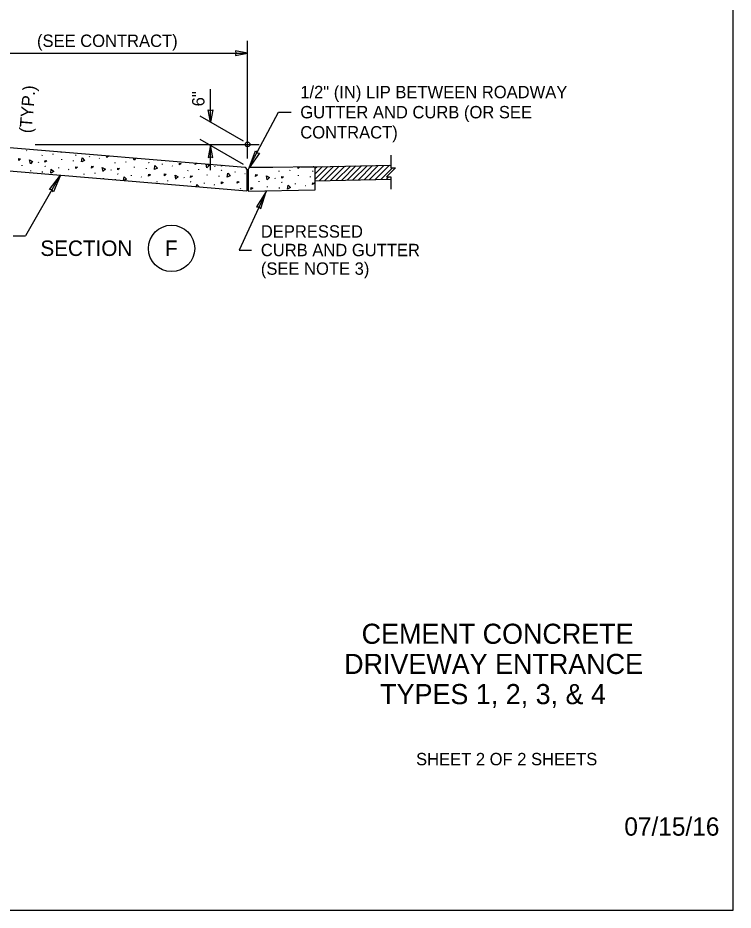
# Model space of a CAD drawing. Extents: x 99862 to 103151, y 100000 to 105076.
# Drawn here: x 102226 to 103151, y 103000 to 104153 of the extents above; entities that cross this region are included whole.
import ezdxf

# ---------------------------------------------------------------- set-up
doc = ezdxf.new("R2010")
doc.units = 0
for name, color, linetype in [('Level 1', 7, 'Continuous'), ('Level 13', 7, 'Continuous'), ('Level 15', 7, 'Continuous'), ('Level 20', 7, 'Continuous'), ('Level 48', 7, 'Continuous'), ('Level 62', 7, 'Continuous'), ('Level 9', 7, 'Continuous')]:
    doc.layers.add(name, color=color, linetype=linetype)

msp = doc.modelspace()

# ---------------------------------------------------------------- linework, layer by layer
at = {"layer": 'Level 1'}
msp.add_lwpolyline([(99862, 102999.5), (103151, 102999.5), (103151, 105075.5), (99862, 105075.5)], close=True, dxfattribs=at)
at = {"layer": 'Level 13'}
for p, q in [((102237.4, 103981.6), (102237.9, 103981.2)), ((102237.4, 103981.6), (102237.9, 103981.2)), ((102257.9, 103975), (102258, 103975.9)), ((102257.9, 103975), (102258, 103975.9)), ((102271.9, 103976.2), (102271.9, 103977.1)), ((102271.9, 103976.2), (102271.9, 103977.1)), ((102283, 103969.3), (102283, 103970.2)), ((102283, 103969.3), (102283, 103970.2)), ((102298.3, 103967.8), (102298.3, 103968.7)), ((102298.3, 103967.8), (102298.3, 103968.7)), ((102300.9, 103975.8), (102301.4, 103975.4)), ((102300.9, 103975.8), (102301.4, 103975.4)), ((102301.3, 103975.7), (102301.8, 103975.4)), ((102301.3, 103975.7), (102301.8, 103975.4)), ((102319.1, 103973.3), (102319.2, 103974.1)), ((102319.1, 103973.3), (102319.2, 103974.1)), ((102331.5, 103971.7), (102332, 103971.3)), ((102331.5, 103971.7), (102332, 103971.3)), ((102386.9, 103970.8), (102387, 103970.7)), ((102386.9, 103970.8), (102387, 103970.7)), ((102231.9, 103961.6), (102232, 103962.5)), ((102231.9, 103961.6), (102232, 103962.5)), ((102252.5, 103966.8), (102252.9, 103966.1)), ((102252.5, 103966.8), (102252.9, 103966.1)), ((102261, 103961.3), (102261.5, 103960.9)), ((102261, 103961.3), (102261.5, 103960.9)), ((102261.4, 103961.2), (102261.9, 103960.8)), ((102261.4, 103961.2), (102261.9, 103960.8)), ((102279.2, 103958.7), (102279.2, 103959.6)), ((102279.2, 103958.7), (102279.2, 103959.6)), ((102291.5, 103957.2), (102292.1, 103956.8)), ((102291.5, 103957.2), (102292.1, 103956.8)), ((102346.6, 103956.9), (102347, 103956.2)), ((102346.6, 103956.9), (102347, 103956.2)), ((102352.1, 103965.1), (102352.1, 103966)), ((102352.1, 103965.1), (102352.1, 103966)), ((102366, 103966.3), (102366.1, 103967.2)), ((102366, 103966.3), (102366.1, 103967.2)), ((102377.1, 103959.4), (102377.2, 103960.3)), ((102377.1, 103959.4), (102377.2, 103960.3)), ((102392.4, 103957.9), (102392.4, 103958.8)), ((102392.4, 103957.9), (102392.4, 103958.8)), ((102395.1, 103965.9), (102395.6, 103965.5)), ((102395.1, 103965.9), (102395.6, 103965.5)), ((102395.5, 103965.9), (102396, 103965.5)), ((102395.5, 103965.9), (102396, 103965.5)), ((102413.3, 103963.4), (102413.3, 103964.3)), ((102413.3, 103963.4), (102413.3, 103964.3)), ((102425.7, 103961.8), (102426.2, 103961.5)), ((102425.7, 103961.8), (102426.2, 103961.5)), ((102460.1, 103956.4), (102460.2, 103957.3)), ((102460.1, 103956.4), (102460.2, 103957.3)), ((102480.7, 103961.6), (102481.1, 103960.8)), ((102480.7, 103961.6), (102481.1, 103960.8)), ((102578, 103955.5), (102578.1, 103956.4)), ((102578, 103955.5), (102578.1, 103956.4)), ((102598.8, 103960.3), (102599, 103959.9)), ((102598.8, 103960.3), (102599, 103959.9)), ((102243, 103954.7), (102243.1, 103955.6)), ((102243, 103954.7), (102243.1, 103955.6)), ((102258.3, 103953.3), (102258.3, 103954.2)), ((102258.3, 103953.3), (102258.3, 103954.2)), ((102312.1, 103950.6), (102312.2, 103951.4)), ((102312.1, 103950.6), (102312.2, 103951.4)), ((102326, 103951.8), (102326.1, 103952.6)), ((102326, 103951.8), (102326.1, 103952.6)), ((102337.1, 103944.9), (102337.2, 103945.7)), ((102337.1, 103944.9), (102337.2, 103945.7)), ((102355.1, 103951.4), (102355.6, 103951)), ((102355.1, 103951.4), (102355.6, 103951)), ((102355.5, 103951.3), (102356, 103950.9)), ((102355.5, 103951.3), (102356, 103950.9)), ((102373.3, 103948.8), (102373.4, 103949.7)), ((102373.3, 103948.8), (102373.4, 103949.7)), ((102385.7, 103947.3), (102386.2, 103946.9)), ((102385.7, 103947.3), (102386.2, 103946.9)), ((102440.8, 103947), (102441.1, 103946.3)), ((102440.8, 103947), (102441.1, 103946.3)), ((102446.2, 103955.2), (102446.3, 103956.1)), ((102446.2, 103955.2), (102446.3, 103956.1)), ((102471.2, 103949.5), (102471.3, 103950.4)), ((102471.2, 103949.5), (102471.3, 103950.4)), ((102486.5, 103948.1), (102486.6, 103948.9)), ((102486.5, 103948.1), (102486.6, 103948.9)), ((102489.2, 103956), (102489.7, 103955.7)), ((102489.2, 103956), (102489.7, 103955.7)), ((102489.6, 103956), (102490.1, 103955.6)), ((102489.6, 103956), (102490.1, 103955.6)), ((102507.4, 103953.5), (102507.5, 103954.4)), ((102507.4, 103953.5), (102507.5, 103954.4)), ((102519.8, 103952), (102520.3, 103951.6)), ((102519.8, 103952), (102520.3, 103951.6)), ((102558.7, 103946.1), (102559, 103945.4)), ((102558.7, 103946.1), (102559, 103945.4)), ((102564.1, 103954.3), (102564.2, 103955.2)), ((102564.1, 103954.3), (102564.2, 103955.2)), ((102589.1, 103948.6), (102589.2, 103949.5)), ((102589.1, 103948.6), (102589.2, 103949.5)), ((102604.4, 103947.1), (102604.5, 103948)), ((102604.4, 103947.1), (102604.5, 103948)), ((102607.1, 103955.1), (102607.6, 103954.7)), ((102607.1, 103955.1), (102607.6, 103954.7)), ((102607.5, 103955), (102608, 103954.7)), ((102607.5, 103955), (102608, 103954.7)), ((102352.4, 103943.7), (102352.5, 103944.3)), ((102352.4, 103943.7), (102352.5, 103944.3)), ((102406.2, 103940.7), (102406.3, 103941.6)), ((102406.2, 103940.7), (102406.3, 103941.6)), ((102420.2, 103941.9), (102420.2, 103942.8)), ((102420.2, 103941.9), (102420.2, 103942.8)), ((102449.2, 103941.5), (102449.7, 103941.1)), ((102449.2, 103941.5), (102449.7, 103941.1)), ((102449.6, 103941.4), (102450.1, 103941)), ((102449.6, 103941.4), (102450.1, 103941)), ((102467.4, 103938.9), (102467.5, 103939.8)), ((102467.4, 103938.9), (102467.5, 103939.8)), ((102479.8, 103937.4), (102480.3, 103937)), ((102479.8, 103937.4), (102480.3, 103937)), ((102524.2, 103940.5), (102524.2, 103940.6)), ((102524.2, 103940.5), (102524.2, 103940.6)), ((102538.1, 103941), (102538.1, 103941.8)), ((102538.1, 103941), (102538.1, 103941.8)), ((102549.2, 103934), (102549.2, 103934.9)), ((102549.2, 103934), (102549.2, 103934.9)), ((102564.4, 103932.6), (102564.5, 103933.5)), ((102564.4, 103932.6), (102564.5, 103933.5)), ((102567.1, 103940.6), (102567.6, 103940.2)), ((102567.1, 103940.6), (102567.6, 103940.2)), ((102567.5, 103940.5), (102568, 103940.1)), ((102567.5, 103940.5), (102568, 103940.1)), ((102585.3, 103938), (102585.4, 103938.9)), ((102585.3, 103938), (102585.4, 103938.9)), ((102597.7, 103936.5), (102598.2, 103936.1)), ((102597.7, 103936.5), (102598.2, 103936.1)), ((102500.4, 103931.3), (102500.4, 103931.7)), ((102500.4, 103931.3), (102500.4, 103931.7)), ((102514.3, 103932), (102514.4, 103932.9)), ((102514.3, 103932), (102514.4, 103932.9))]:
    msp.add_line(p, q, dxfattribs=at)
for points in [[(102282.3, 103979), (102282.2, 103979.5)], [(102282.3, 103979), (102282.2, 103979.5)], [(102282.8, 103979.5), (102282.4, 103979.1)], [(102282.8, 103979.5), (102282.4, 103979.1)], [(102227.4, 103968.8), (102227.7, 103971.2), (102229.8, 103970.6), (102227.4, 103968.8)], [(102227.4, 103968.8), (102227.7, 103971.2), (102229.8, 103970.6), (102227.4, 103968.8)], [(102242.4, 103964.5), (102241.3, 103969.5), (102245.4, 103967.5), (102242.4, 103964.5)], [(102242.4, 103964.5), (102241.3, 103969.5), (102245.4, 103967.5), (102242.4, 103964.5)], [(102261.3, 103966.3), (102261.5, 103968.7), (102263.7, 103968.1), (102261.3, 103966.3)], [(102261.3, 103966.3), (102261.5, 103968.7), (102263.7, 103968.1), (102261.3, 103966.3)], [(102308.7, 103966.9), (102309.4, 103972), (102312.6, 103968.7), (102308.8, 103966.9)], [(102308.7, 103966.9), (102309.4, 103972), (102312.6, 103968.7), (102308.8, 103966.9)], [(102341.1, 103972.7), (102341.3, 103974.6)], [(102341.1, 103972.7), (102341.3, 103974.6)], [(102343.3, 103974.4), (102341.1, 103972.7)], [(102343.3, 103974.4), (102341.1, 103972.7)], [(102376.5, 103969.1), (102375.9, 103971.7)], [(102376.5, 103969.1), (102375.9, 103971.7)], [(102378.8, 103971.5), (102376.5, 103969.2)], [(102378.8, 103971.5), (102376.5, 103969.2)], [(102268.7, 103952.4), (102269.4, 103957.4), (102272.6, 103954.2), (102268.8, 103952.4)], [(102268.7, 103952.4), (102269.4, 103957.4), (102272.6, 103954.2), (102268.8, 103952.4)], [(102301.1, 103958.2), (102301.3, 103960.6), (102303.5, 103960), (102301.1, 103958.2)], [(102301.1, 103958.2), (102301.3, 103960.6), (102303.5, 103960), (102301.1, 103958.2)], [(102321.6, 103958.9), (102321.8, 103961.3), (102323.9, 103960.7), (102321.6, 103958.9)], [(102321.6, 103958.9), (102321.8, 103961.3), (102323.9, 103960.7), (102321.6, 103958.9)], [(102336.5, 103954.6), (102335.4, 103959.6), (102339.5, 103957.6), (102336.6, 103954.7)], [(102336.5, 103954.6), (102335.4, 103959.6), (102339.5, 103957.6), (102336.6, 103954.7)], [(102355.4, 103956.4), (102355.7, 103958.9), (102357.8, 103958.2), (102355.4, 103956.4)], [(102355.4, 103956.4), (102355.7, 103958.9), (102357.8, 103958.2), (102355.4, 103956.4)], [(102402.8, 103957), (102403.5, 103962.1), (102406.7, 103958.8), (102402.9, 103957.1)], [(102402.8, 103957), (102403.5, 103962.1), (102406.7, 103958.8), (102402.9, 103957.1)], [(102435.2, 103962.9), (102435.4, 103965.3), (102437.6, 103964.7), (102435.2, 103962.9)], [(102435.2, 103962.9), (102435.4, 103965.3), (102437.6, 103964.7), (102435.2, 103962.9)], [(102455.7, 103963.5), (102455.8, 103965)], [(102455.7, 103963.5), (102455.8, 103965)], [(102457.4, 103964.9), (102455.7, 103963.5)], [(102457.4, 103964.9), (102455.7, 103963.5)], [(102470.6, 103959.3), (102469.6, 103963.9)], [(102470.6, 103959.3), (102469.6, 103963.9)], [(102470.5, 103963.8), (102473.6, 103962.3), (102470.7, 103959.3)], [(102470.5, 103963.8), (102473.6, 103962.3), (102470.7, 103959.3)], [(102489.5, 103961.1), (102489.6, 103962.2)], [(102489.5, 103961.1), (102489.6, 103962.2)], [(102490.9, 103962.1), (102489.5, 103961.1)], [(102490.9, 103962.1), (102489.5, 103961.1)], [(102524.5, 103958), (102524.6, 103957.9), (102524.4, 103957.8)], [(102524.5, 103958), (102524.6, 103957.9), (102524.4, 103957.8)], [(102588.5, 103958.3), (102588.1, 103960.1)], [(102588.5, 103958.3), (102588.1, 103960.1)], [(102590.3, 103960.1), (102588.6, 103958.4)], [(102590.3, 103960.1), (102588.6, 103958.4)], [(102607.4, 103960.2), (102607.5, 103960.5)], [(102607.8, 103960.5), (102607.4, 103960.2)], [(102607.4, 103960.2), (102607.5, 103960.5)], [(102607.8, 103960.5), (102607.4, 103960.2)], [(102362.9, 103942.8), (102363.6, 103947.6), (102366.7, 103944.3), (102363.4, 103942.7)], [(102395.2, 103948.3), (102395.5, 103950.8), (102397.6, 103950.1), (102395.2, 103948.3)], [(102395.2, 103948.3), (102395.5, 103950.8), (102397.6, 103950.1), (102395.2, 103948.3)], [(102415.7, 103949), (102415.9, 103951.5), (102418.1, 103950.8), (102415.7, 103949)], [(102415.7, 103949), (102415.9, 103951.5), (102418.1, 103950.8), (102415.7, 103949)], [(102430.6, 103944.7), (102429.5, 103949.7), (102433.7, 103947.7), (102430.7, 103944.8)], [(102430.6, 103944.7), (102429.5, 103949.7), (102433.7, 103947.7), (102430.7, 103944.8)], [(102449.6, 103946.5), (102449.8, 103949), (102451.9, 103948.3), (102449.6, 103946.5)], [(102449.6, 103946.5), (102449.8, 103949), (102451.9, 103948.3), (102449.6, 103946.5)], [(102497, 103947.1), (102497.7, 103952.2), (102500.8, 103948.9), (102497, 103947.2)], [(102497, 103947.1), (102497.7, 103952.2), (102500.8, 103948.9), (102497, 103947.2)], [(102533.6, 103948.1), (102533.8, 103950.5), (102536, 103949.9), (102533.6, 103948.1)], [(102533.6, 103948.1), (102533.8, 103950.5), (102536, 103949.9), (102533.6, 103948.1)], [(102548.5, 103943.8), (102547.5, 103948.8), (102551.6, 103946.8), (102548.6, 103943.8)], [(102548.5, 103943.8), (102547.5, 103948.8), (102551.6, 103946.8), (102548.6, 103943.8)], [(102567.5, 103945.6), (102567.7, 103948.1), (102569.8, 103947.4), (102567.5, 103945.6)], [(102567.5, 103945.6), (102567.7, 103948.1), (102569.8, 103947.4), (102567.5, 103945.6)], [(102457.3, 103934.9), (102457.7, 103937.7), (102460.6, 103934.6)], [(102457.3, 103934.9), (102457.7, 103937.7), (102460.6, 103934.6)], [(102489.4, 103938.4), (102489.6, 103940.9), (102491.7, 103940.2), (102489.4, 103938.4)], [(102489.4, 103938.4), (102489.6, 103940.9), (102491.7, 103940.2), (102489.4, 103938.4)], [(102509.8, 103939.1), (102510.1, 103941.6), (102512.2, 103940.9), (102509.8, 103939.1)], [(102509.8, 103939.1), (102510.1, 103941.6), (102512.2, 103940.9), (102509.8, 103939.1)], [(102527.5, 103931.1), (102527.7, 103933.5), (102529.9, 103932.9), (102527.5, 103931.1)], [(102527.5, 103931.1), (102527.7, 103933.5), (102529.9, 103932.9), (102527.5, 103931.1)], [(102574.9, 103931.7), (102575.6, 103936.7), (102578.8, 103933.5), (102575, 103931.7)], [(102574.9, 103931.7), (102575.6, 103936.7), (102578.8, 103933.5), (102575, 103931.7)], [(102607.3, 103937.5), (102607.5, 103939.9), (102609.6, 103939.3), (102607.3, 103937.5)], [(102607.3, 103937.5), (102607.5, 103939.9), (102609.6, 103939.3), (102607.3, 103937.5)]]:
    msp.add_lwpolyline(points, dxfattribs=at)
at = {"layer": 'Level 15'}
for p, q in [((102523.2, 103971.4), (102523.2, 104123.4)), ((102523.2, 103971.4), (102523.2, 104123.4)), ((102163.2, 104107.4), (102523.2, 104107.4)), ((102475.5, 104018.3), (102475.5, 104060.9)), ((102475.5, 104018.3), (102475.5, 104060.9)), ((102461.6, 104026.3), (102517.7, 103993.9)), ((102525.7, 103960.8), (102563.4, 104031.1)), ((102525.7, 103960.8), (102563.4, 104031.1)), ((102563.4, 104031.1), (102579.4, 104031.1)), ((102563.4, 104031.1), (102579.4, 104031.1)), ((102461.6, 103996.3), (102517.7, 103963.9)), ((102248.5, 103989.4), (102502.9, 103989.4)), ((102475.5, 103956.3), (102475.5, 103988.3)), ((102475.5, 103956.3), (102475.5, 103988.3)), ((102502.9, 103989.4), (102538.2, 103989.4)), ((102511.7, 103989.4), (102538.2, 103989.4)), ((102610.7, 103958.5), (102612.8, 103960.6)), ((102280.7, 103948.6), (102236, 103871.2)), ((102547.1, 103928.4), (102512.4, 103852.9)), ((102547.1, 103928.4), (102512.4, 103852.9)), ((102220, 103871.2), (102236, 103871.2)), ((102512.4, 103852.9), (102528.4, 103852.9)), ((102512.4, 103852.9), (102528.4, 103852.9))]:
    msp.add_line(p, q, dxfattribs=at)
for points in [[(102523.2, 104107.4), (102507.5, 104110.5), (102508.2, 104107.4), (102507.5, 104104.3)], [(102523.2, 104107.4), (102507.5, 104110.5), (102508.2, 104107.4), (102507.5, 104104.3)], [(102475.5, 104018.3), (102472.4, 104034), (102475.5, 104033.3), (102478.5, 104034)], [(102475.5, 104018.3), (102472.4, 104034), (102475.5, 104033.3), (102478.5, 104034)], [(102475.5, 103988.3), (102472.4, 103972.6), (102475.5, 103973.3), (102478.5, 103972.6)], [(102475.5, 103988.3), (102472.4, 103972.6), (102475.5, 103973.3), (102478.5, 103972.6)], [(102525.2, 103959.3), (102533.3, 103980.9), (102535.5, 103978.5), (102538.6, 103978.1)], [(102525.2, 103959.3), (102533.3, 103980.9), (102535.5, 103978.5), (102538.6, 103978.1)], [(102281.3, 103949.6), (102272.4, 103928.3), (102270.4, 103930.7), (102267.3, 103931.3)], [(102547.1, 103928.4), (102534.9, 103908.9), (102538, 103908.6), (102540.3, 103906.4)], [(102547.1, 103928.4), (102534.9, 103908.9), (102538, 103908.6), (102540.3, 103906.4)]]:
    msp.add_lwpolyline(points, close=True, dxfattribs=at)
msp.add_lwpolyline([(102708.6, 103975.3), (102708.6, 103959.3), (102714.4, 103959.3), (102702.8, 103947.7), (102708.6, 103947.7), (102708.6, 103931.7)], dxfattribs=at)
msp.add_lwpolyline([(102708.6, 103975.3), (102708.6, 103959.3), (102714.4, 103959.3), (102702.8, 103947.7), (102708.6, 103947.7), (102708.6, 103931.7)], dxfattribs=at)
msp.add_circle((102523.2, 103989.4), 3.08, dxfattribs=at)
msp.add_circle((102523.2, 103989.4), 3.08, dxfattribs=at)
at = {"layer": 'Level 20'}
for p, q in [((102520, 103959.7), (102166, 103989.2)), ((102163.2, 103959.4), (102522.3, 103929.5)), ((102522.3, 103957.2), (102522.3, 103929.5)), ((102524.2, 103956.9), (102524.2, 103928.8)), ((102555.7, 103959.4), (102526.7, 103959.4)), ((102608.2, 103960.5), (102555.7, 103959.4)), ((102610.7, 103930.5), (102610.7, 103958)), ((102610.7, 103930.5), (102610.7, 103958)), ((102524.2, 103928.8), (102610.7, 103930.5))]:
    msp.add_line(p, q, dxfattribs=at)
for centre, start, end in [((102519.8, 103957.2), 0, 85.2364), ((102519.8, 103957.2), 0, 85.2364), ((102526.7, 103956.9), 90, 180), ((102526.7, 103956.9), 90, 180), ((102608.2, 103958), 0, 91.1458), ((102608.2, 103958), 0, 91.1458)]:
    msp.add_arc(centre, 2.5, start, end, dxfattribs=at)
at = {"layer": 'Level 48'}
for p, q in [((102592, 103960.1), (102708.6, 103962.5)), ((102610.7, 103960.5), (102708.6, 103962.5)), ((102610.7, 103944.4), (102627.2, 103960.8)), ((102610.7, 103951.4), (102620, 103960.7)), ((102616.1, 103942.6), (102634.4, 103961)), ((102623.3, 103942.8), (102641.7, 103961.1)), ((102630.5, 103942.9), (102648.9, 103961.3)), ((102637.7, 103943.1), (102656.1, 103961.4)), ((102644.9, 103943.2), (102663.3, 103961.6)), ((102652.1, 103943.3), (102670.5, 103961.7)), ((102659.4, 103943.5), (102677.7, 103961.9)), ((102666.6, 103943.6), (102684.9, 103962)), ((102673.8, 103943.8), (102692.2, 103962.1)), ((102681, 103943.9), (102699.4, 103962.3)), ((102688.2, 103944.1), (102706.6, 103962.4)), ((102695.4, 103944.2), (102710.5, 103959.3)), ((102702.7, 103944.4), (102706, 103947.7)), ((102610.7, 103942.5), (102708.6, 103944.5)), ((102610.7, 103942.5), (102708.6, 103944.5))]:
    msp.add_line(p, q, dxfattribs=at)
at = {"layer": 'Level 9'}
msp.add_circle((102425, 103855), 30, dxfattribs=at)
msp.add_circle((102425, 103855), 30, dxfattribs=at)

# ---------------------------------------------------------------- texts
at = {"layer": 'Level 15'}
msp.add_text('07/15/16', height=23.62, dxfattribs=at).set_placement((103010.3, 103095.8))
at = {"layer": 'Level 20'}
for s, height, p in [('(SEE CONTRACT)', 16, (102251, 104115.4)), ('1/2" (IN) LIP BETWEEN ROADWAY', 16, (102591.4, 104049.1)), ('GUTTER AND CURB (OR SEE', 16, (102591.4, 104023.1)), ('CONTRACT)', 16, (102591.4, 103997.1)), ('DEPRESSED', 16, (102540.4, 103868.9)), ('SECTION', 20, (102255.4, 103845.2)), ('F', 20, (102416.5, 103845.2)), ('CURB AND GUTTER', 16, (102540.4, 103844.9)), ('(SEE NOTE 3)', 16, (102540.4, 103820.9))]:
    msp.add_text(s, height=height, dxfattribs=at).set_placement(p)
for s, rotation, p in [('(TYP.)', 85.237, (102244, 104003.5)), ('6"', 90, (102467.5, 104038.6))]:
    msp.add_text(s, height=16, rotation=rotation, dxfattribs=at).set_placement(p)
at = {"layer": 'Level 62'}
for s, height, p in [('CEMENT CONCRETE', 26, (102670.7, 103343.8)), ('CEMENT CONCRETE', 26, (102670.7, 103343.8)), ('DRIVEWAY ENTRANCE', 26, (102648.1, 103304.8)), ('DRIVEWAY ENTRANCE', 26, (102648.1, 103304.8)), ('TYPES 1, 2, 3, & 4', 26, (102694.7, 103265.8)), ('TYPES 1, 2, 3, & 4', 26, (102694.7, 103265.8)), ('SHEET 2 OF 2 SHEETS', 16, (102741.1, 103186.8))]:
    msp.add_text(s, height=height, dxfattribs=at).set_placement(p)

doc.saveas('drawing.dxf')
